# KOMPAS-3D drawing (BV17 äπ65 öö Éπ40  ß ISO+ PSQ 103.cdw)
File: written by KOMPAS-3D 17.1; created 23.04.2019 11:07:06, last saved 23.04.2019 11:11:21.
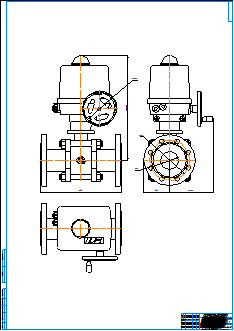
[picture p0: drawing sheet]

Sheet 1: A0, portrait

Title block, sheet 1: name: BV17 Ду65 ФФ Ру40 / с ISO+ PSQ 103; material: Внимание! Данный продукт является объектом авторского права ООО «Торговый Дом АДЛ». / Запрещается изменение, копирование, распространение / (в том числе путем копирования на другие сайты и ресурсы в Интернете) / или любое иное использование информации и объектов без предварительного / согласия правообладателя (ООО «Торговый Дом АДЛ»).; mass: 59,71; sheets: 1; organisation: ООО "Торговый дом АДЛ"; sheet format: A0

Views: Вид 1, Проекционный вид 2, Проекционный вид 3
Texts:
  user
Dimensions and other numbers on the sheet: 376,55; 290; 126,4; 92,5; 156,34; 145; 65; 1:1; 1; 59,71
